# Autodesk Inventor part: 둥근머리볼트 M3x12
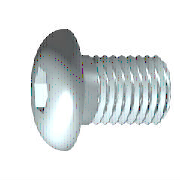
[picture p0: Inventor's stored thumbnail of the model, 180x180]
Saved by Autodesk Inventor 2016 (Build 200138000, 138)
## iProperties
IsCustomPart: 0
Created: 2012-02
Part Number: 둥근머리볼트 M3x12
Material: 강철
Description: 6각 소켓 버튼 머리 나사 - 제품 등급 A
Document SubType Name: Modeling
Standard: ISO 7380
Designer: mduedu
Standard Revision: Third edition 2004-01-15
Standards Organization: ISO
Language: ko-KR
Size Designation: M3 x 12
Categories: <MemberInstance><Categories><Category DisplayName="조임쇠" InternalName="e4da775c-781d-43d5-af7c-5136215cf5a6" Mnemonic="FSTN"><Category DisplayName="볼트" InternalN
Density: 7.85 g/cm^3
Appearance: 강철
Mass: 0.90169 g
Surface Area: 1.87531 cm^2
Volume: 0.114865 cm^3
Author: mduedu
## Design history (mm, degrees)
sketch "스케치1"
  geometry: L1 (0.057, 0)-(12, 0); L2 (12, 0)-(12, 1.5); L3 (12, 1.5)-(1, 1.5); L4 (1, 1.5)-(0.693, 1.5); L5 (0.693, 1.5)-(0, 1.5); L6 (0, 1.5)-(0, 2.85); L7 (0, 2.85)-(-1.65, 2.85); L8 (-1.65, 2.85)-(-1.65, 1.155); L9 (-1.65, 1.155)-(-0.61, 1.155); L10 (-0.61, 1.155)-(0.057, 0); L11 (-4.38, 0)-(14.73, 0) reference; L12 (0, -0.57)-(0, 3.42) reference; L13 (1, 1.5)-(0, 1.5)
  constraints: 22 end point, 6 parallel, 2 collinear, 2 perpendicular, 1 horizontal, 1 point on line
  dimensions: "d1" = 11 distance from line of L3.end L2 (= GEL); "d2" = 0.30683 distance of L4.end L3.end (computed from GAL); "d3" = 1.65 distance between parallel lines of L8 L6 (= KOH); "d4" = 1.04 distance of L8.end L9.end (= INTI); "d5" = 60 deg angle of L10 L1; "d6" = 3 diameter of L3 L1 (= GD); "d7" = 3 diameter of L5 L1 (= BDM); "d8" = 2.3094 diameter of L9 L1 (= 1.1547 x SW); "d9" = 5.7 diameter of L7 L1 (= KOD); "d26" = 12 distance between parallel lines of L12 L2 (= NLG)
revolve "본체" sketch "스케치1" stored, may be unused: angle "d10" = 90 deg
sketch "스케치2"
  geometry: L1 (0, -3.99)-(0, 3.99) reference; L2 (-3.99, 0)-(3.99, 0) reference; L3 (1.155, 0)-(0.577, -1); L4 (0.577, -1)-(-0.577, -1); L5 (-0.577, -1)-(-1.155, 0); L6 (-1.155, 0)-(-0.577, 1); L7 (-0.577, 1)-(0.577, 1); L8 (0.577, 1)-(1.155, 0); 2 further points
  constraints: 12 end point, 1 coincident, 1 horizontal alignment, 1 point on line, 12 other
extrude "슬롯" join sketch "스케치2" stored distance "d11" = 10; taper "d12" = 0 deg
workplane "Work Plane1"
body "Solid1"
fillet "모깎기1" dims "d17" = 1.45 (= RR)
feature "스레드" dims "d13" = 11 (= GEL), "d14" = 0
chamfer "모따기1" distance "d15" = 0.30673 (= -0.5 x SPD + 0.5 x GD); stored, may be unused: second distance "d16" = 0.30673 (= GUL), angle "d27" = 45 deg
fillet "모깎기2" dims "d30" = 0.1 (= R)
other parameters: "GD" = 3 (= NND) [user parameter; used in 2 equation terms], "NLG" = 12 [user parameter; used in 1 equation term], "GEL" = 11 [user parameter; used in 2 equation terms], "KOD" = 5.7 [user parameter; used in 1 equation term], "KOH" = 1.65 [user parameter; used in 1 equation term], "INTI" = 1.04 [user parameter; used in 1 equation term], "GAL" = 0.30673 (= 0.61345 x PTC) [user parameter; used in 1 equation term], "GUL" = 0.30673 (= 0.61345 x PTC) [user parameter; used in 1 equation term], "BDM" = 3 (= NND) [user parameter; used in 1 equation term], "SW" = 2 [user parameter; used in 1 equation term], "RR" = 1.45 [user parameter; used in 1 equation term], "SPD" = 2.38655 (= NND - 1.2269 x PTC) [user parameter; used in 1 equation term], "d19" = 0, "d28" = 0, "d29" = 0, "R" = 0.1 [user parameter; used in 1 equation term], "TOA" = 30 deg [user parameter], "GD1" = 2.38655 (= THREADDIA - 1.2269 x PTC) [user parameter], "THREADDIA" = 3 [user parameter; used in 1 equation term], "PTC" = 0.5 [user parameter; used in 5 equation terms], "NND" = 3 [user parameter; used in 3 equation terms], "KOH1" = 0.2 [user parameter], "E0" = 2.31 [user parameter]
